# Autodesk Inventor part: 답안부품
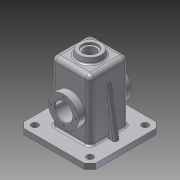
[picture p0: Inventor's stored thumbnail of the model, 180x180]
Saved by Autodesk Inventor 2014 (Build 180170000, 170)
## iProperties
Created: 2016-02
Part Number: 답안부품
Material: 알루미늄 6061
Document SubType Name: Modeling
Designer: 703-6
Density: 2.71 g/cm^3
Appearance: 알루미늄 - 평지
Mass: 934.037 g
Surface Area: 1076.57 cm^2
Volume: 344.663 cm^3
Author: 703-6
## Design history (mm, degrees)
sketch "스케치1"
  geometry: L1 (-65, 65)-(65, 65); L2 (65, 65)-(65, -65); L3 (65, -65)-(-65, -65); L4 (-65, -65)-(-65, 65); 1 further point
  constraints: 8 end point, 2 parallel, 1 horizontal, 1 perpendicular
  dimensions: "d0" = 130 distance of L1.start L1.end; "d1" = 130 distance of L1.end L2.end; "d2" = 65 distance from line of point (0, 0) L1; "d3" = 65 distance from line of point (0, 0) L2
extrude "돌출1" new body sketch "스케치1" distance "d4" = 10; taper "d5" = 0 deg
sketch "스케치2"
  geometry: L1 (-35, 35)-(35, 35); L2 (35, 35)-(35, -35); L3 (35, -35)-(-35, -35); L4 (-35, -35)-(-35, 35); 1 further point
  constraints: 8 end point, 2 parallel, 1 horizontal, 1 perpendicular
  dimensions: "d6" = 70 distance of L1.start L1.end; "d7" = 70 distance of L3.end L1.start; "d8" = 35 distance from line of point (0, 0) L1; "d9" = 35 distance from line of point (0, 0) L4
extrude "돌출2" join sketch "스케치2" distance "d10" = 110; taper "d11" = 0 deg
sketch "스케치3"
  geometry: L1 (65, 10)-(65, 0) reference; L2 (65, 0)-(-65, 0) reference; L3 (-65, 0)-(-65, 10) reference; L4 (-65, 10)-(-35, 10) reference; L5 (-35, 10)-(-35, 120) reference; L6 (-35, 120)-(35, 120) reference; L7 (35, 120)-(35, 10) reference; L8 (35, 10)-(65, 10) reference; L9 (-50, 10)-(-35, 95.069); L10 (-50, 10)-(-35, 10); L11 (-35.07, 94.672)-(-35.07, 10); 1 further point
  constraints: 6 end point, 4 point on line, 2 perpendicular
  dimensions: "d12" = 15 distance from line of L9.start L3; "d13" = 10 distance from line of L9.start L2; "d14" = 10 deg angle of L9 L3; "d15" = 35 distance from line of point (0, 0) L5 (derived); "d16" = 94.67177 distance from line of L2 L11.start
extrude "돌출3" join sketch "스케치3" stored distance "d17" = 10; taper "d18" = 0 deg
sketch "스케치4"
  geometry: L1 (65, 10)-(65, 0) reference; L2 (65, 0)-(-65, 0) reference; L3 (-65, 0)-(-65, 10) reference; L4 (-65, 10)-(-50, 10) reference; L5 (-50, 10)-(-35.07, 94.672) reference; L6 (-35.07, 94.672)-(-35.07, 10) reference; L7 (-35.07, 10)-(-35, 10) reference; L8 (-35, 10)-(-35, 120) reference; L9 (-35, 120)-(35, 120) reference; L10 (35, 120)-(35, 10) reference; L11 (35, 10)-(35.07, 10) reference; L12 (35.07, 10)-(35.07, 94.672) reference; L13 (35.07, 94.672)-(50, 10) reference; L14 (50, 10)-(65, 10) reference; L15 (-30, 115)-(30.07, 115); L16 (30.07, 115)-(30.07, 0); L17 (30.07, 0)-(-30, 0); L18 (-30, 0)-(-30, 115); 1 further point
  constraints: 8 end point, 2 parallel, 1 horizontal, 1 perpendicular
  dimensions: "d19" = 5 distance between parallel lines of L9 L15; "d20" = 5 distance from line of L12.end L16; "d21" = 5 distance between parallel lines of L8 L18; "d22" = 0 distance between parallel lines of L17 L2
extrude "돌출4" cut sketch "스케치4" stored distance "d23" = 60; taper "d24" = 0 deg
sketch "스케치5"
  geometry: L1 (65, 10)-(65, 0) reference; L2 (65, 0)-(30, 0) reference; L3 (30, 0)-(30, 115) reference; L4 (30, 115)-(-30, 115) reference; L5 (-30, 115)-(-30, 0) reference; L6 (-30, 0)-(-65, 0) reference; L7 (-65, 0)-(-65, 10) reference; L8 (-65, 10)-(-35, 10) reference; L9 (-35, 10)-(-35, 120) reference; L10 (-35, 120)-(35, 120) reference; L11 (35, 120)-(35, 10) reference; L12 (35, 10)-(65, 10) reference; L13 (30, 82.5)-(23, 75.5); L14 (30, 82.5)-(30, 55); L15 (30, 55)-(23, 55); L16 (23, 75.5)-(23, 55); 1 further point
  constraints: 8 end point, 1 parallel, 1 perpendicular, 1 point on line
  dimensions: "d26" = 135 deg angle of L13 L3; "d28" = 7 horizontal distance of L13.start L13.end; "d29" = 55 distance from line of point (0, 0) L15; "d30" = 27.5 vertical distance of L15.end L13.start; "d31" = 30 distance from line of point (0, 0) L14
revolve "회전1" sketch "스케치5" stored, may be unused: angle "d32" = 90 deg
sketch "스케치6"
  geometry: L1 (-30, 10)-(100, 10) reference; C1 r 27.5 at (35, -45); 2 further points
  constraints: 1 centre point, 1 midpoint, 1 vertical alignment
  dimensions: "d33" = 55 diameter of C1; "d34" = 55 distance from line of C1.centre L1
extrude "돌출5" join sketch "스케치6" distance "d35" = 13; taper "d36" = 0 deg
sketch "스케치7"
  geometry: C1 r 27.5 at (0, 0) reference; 1 further point
hole "구멍1" sketch "스케치7" at (0, 0) diameter "d37" = 32; stored, may be unused: countersink angle "d41" = 90 deg, drill point angle "d43" = 118 deg; dims "d38" = 6, "d39" = 4, "d40" = 2, "d42" = 8
sketch "스케치8"
  geometry: C1 r 16 at (0, 0) reference; 2 further points
  dimensions: "d44" = 22.5 distance of point (0, -22.5) C1.centre; "d45" = 0 horizontal distance of C1.centre point (0, -22.5)
hole "구멍2" sketch "스케치8" at (0, -22.5) diameter "d46" = 3.242; stored, may be unused: countersink angle "d50" = 82 deg, drill point angle "d52" = 118 deg; dims "d47" = 8, "d48" = 3.023, "d49" = 2, "d51" = 10
sketch "스케치9"
  geometry: L1 (21.763, 120)-(20, 130); L2 (-35, 120)-(35, 120) reference; L3 (35, 10)-(35, 120) reference; L4 (20, 130)-(0, 130); L5 (21.763, 120)-(0, 120); L6 (0, 120)-(0, 130); 1 further point
  constraints: 8 end point, 2 perpendicular, 1 midpoint
  dimensions: "d56" = 10 vertical distance of L1.start L1.end; "d57" = 0 distance from line of L1.start L2; "d61" = 10 deg angle of L1 L3; "d62" = 20 horizontal distance of point (0, 0) L1.end; "d63" = 20 distance from line of L1.end L6
revolve "회전2" sketch "스케치9" stored, may be unused: angle "d64" = 90 deg
sketch "스케치10"
  geometry: C1 r 20 at (0, 0) reference
hole "구멍3" sketch "스케치10" at (0, 0) diameter "d65" = 21; stored, may be unused: countersink angle "d69" = 82 deg, drill point angle "d71" = 118 deg; dims "d66" = 6, "d67" = 28, "d68" = 4, "d70" = 8
fillet "모깎기1" dims "d72" = 3
sketch "스케치11"
  geometry: L1 (65, 65)-(-65, 65) reference; L2 (-65, 65)-(-65, -65) reference; C1 r 6 at (-50, 50); 1 further point
  constraints: 1 centre point
  dimensions: "d73" = 12 diameter of C1; "d74" = 15 distance from line of C1.centre L1; "d75" = 15 distance from line of C1.centre L2
extrude "돌출6" cut sketch "스케치11" distance "d76" = 10; taper "d77" = 0 deg
fillet "모깎기2" dims "d84" = 3
fillet "모깎기3" dims "d85" = 8
fillet "모깎기4" dims "d86" = 3
fillet "모깎기5" dims "d87" = 3
chamfer "모따기1" distance "d88" = 10; stored, may be unused: second distance "d89" = 2, angle "d90" = 45 deg
chamfer "모따기2" distance "d91" = 10; stored, may be unused: second distance "d92" = 2, angle "d93" = 45 deg
chamfer "모따기3" distance "d94" = 10; stored, may be unused: second distance "d95" = 2, angle "d96" = 45 deg
fillet "모깎기6" dims "d97" = 0.5
fillet "모깎기7" dims "d98" = 0.5
fillet "모깎기8" dims "d99" = 0.5
sketch "스케치12"
  geometry: L1 (44.216, 6.998)-(9.784, 6.998); L2 (9.784, 6.998)-(9.784, 17.002); L3 (9.784, 17.002)-(44.216, 17.002); L4 (44.216, 17.002)-(44.216, 6.998); L5 (-8, 99)-(-8, 0) reference; L6 (47, -18)-(7, -18) reference; 3 further points
  constraints: 2 midpoint, 2 other
  dimensions: "d100" = 35 distance from line of point (27, 6.998) L5; "d101" = 30 distance from line of point (9.784, 12) L6; "d102" = 24.99814 distance from line of point (27, 6.998) L6; "d103" = 17.78431 distance from line of L5 point (9.784, 12)
feature "엠보싱1" sketch "스케치12" dims "d12" = 15, "d13" = 10, "d14" = 10 deg, "d16" = 94.67177, "d104" = 0.5, "d105" = 0
chamfer "모따기4" distance "d106" = 1; stored, may be unused: second distance "d107" = 2, angle "d108" = 45 deg
chamfer "모따기5" distance "d109" = 1; stored, may be unused: second distance "d110" = 2, angle "d111" = 45 deg
node "솔리드1"
mirror "대칭1"
mirror "대칭2"
pattern_circular "원형 패턴1" dims angle "d54" = 360 deg
mirror "대칭3"
pattern_linear "직사각형 패턴1" dims "d80" = 100
node "절단 모서리 투영1"
node "절단 모서리 투영2"
node "절단 모서리 투영3"
other parameters: "d25" = 55, "d27" = 27.5
